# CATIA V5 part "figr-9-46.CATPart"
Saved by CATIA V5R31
Part number: Part1
Bounding box of the stored display mesh (mm): x -159.661 to 182.627, y -78.048 to 78.048, z 0 to 72.429
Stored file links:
  D:\PROJECTS\Project 2021\US EDITION\CATIA V5 6R 2021\Resources\Part Files\c09_catia_v5_6r2021_prt\c09_catia_v5_6r2021_prt\figr-9-46.CATPart
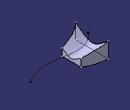
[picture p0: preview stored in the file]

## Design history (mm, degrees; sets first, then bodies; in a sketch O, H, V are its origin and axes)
Body1 (main body)
  Plane1: type Offset, RefPlane yz-plane, Offset 100
  Plane2: type Offset, RefPlane yz-plane, Offset 100, reversed
  Sketch1 on Plane1, origin (100, 0, 0), H (0, 1, 0), V (0, 0, 1)
    point P1 (0, 15.965)
    hyperbola C1
    point P2 (0, 3.0416)
    line L1 (54.8261, 44.8858) -> (54.8261, 0)
    point P5 (54.8261, 0)
    line L2 (-54.8261, 44.8858) -> (-54.8261, 0)
    point P6 (-54.8261, 0)
    line L3 (-54.8261, 0) -> (54.8261, 0)
    coincidence: P1 V, P2 V, P5 H, P6 H
    vertical: L1 V, L2 V
    horizontal: L3 H
  Sketch2 on xy-plane, origin (0, 0, 0), H (1, 0, 0), V (0, 1, 0)
    spline S1 through (-159.6608, -77.1468) (-77.8466, -31.8169) (23.6283, -41.4968) (182.6271, -11.7333)
  Sketch3 on yz-plane, origin (0, 0, 0), H (0, 1, 0), V (0, 0, 1)
    point P1 (0, 18.9787)
    hyperbola C1
    point P2 (0, 2.6681)
    line L1 (48.2237, 37.1764) -> (48.2237, 0)
    point P5 (48.2237, 0)
    line L2 (-43.6563, 34.1546) -> (-43.6563, 0)
    point P6 (-43.6563, 0)
    line L3 (-43.6563, 0) -> (48.2237, 0)
    coincidence: P1 V, P2 V, P5 H, P6 H
    vertical: L1 V, L2 V
    horizontal: L3 H
  Sketch4 on Plane2, origin (-100, 0, 0), H (0, 1, 0), V (0, 0, 1)
    point P1 (0, 140.6052)
    point P2 (0, 41.8972)
    hyperbola C1
    line L1 (78.0478, 72.4293) -> (78.0478, 0)
    point P5 (78.0478, 0)
    line L2 (-78.0478, 72.4293) -> (-78.0478, 0)
    point P6 (-78.0478, 0)
    line L3 (-78.0478, 0) -> (78.0478, 0)
    coincidence: P1 V, P2 V, P5 H, P6 H
    vertical: L1 V, L2 V
    horizontal: L3 H
  Loft1: solid, Sections (Sketch3; Sketch4), Spine Sketch2
  Loft2: solid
